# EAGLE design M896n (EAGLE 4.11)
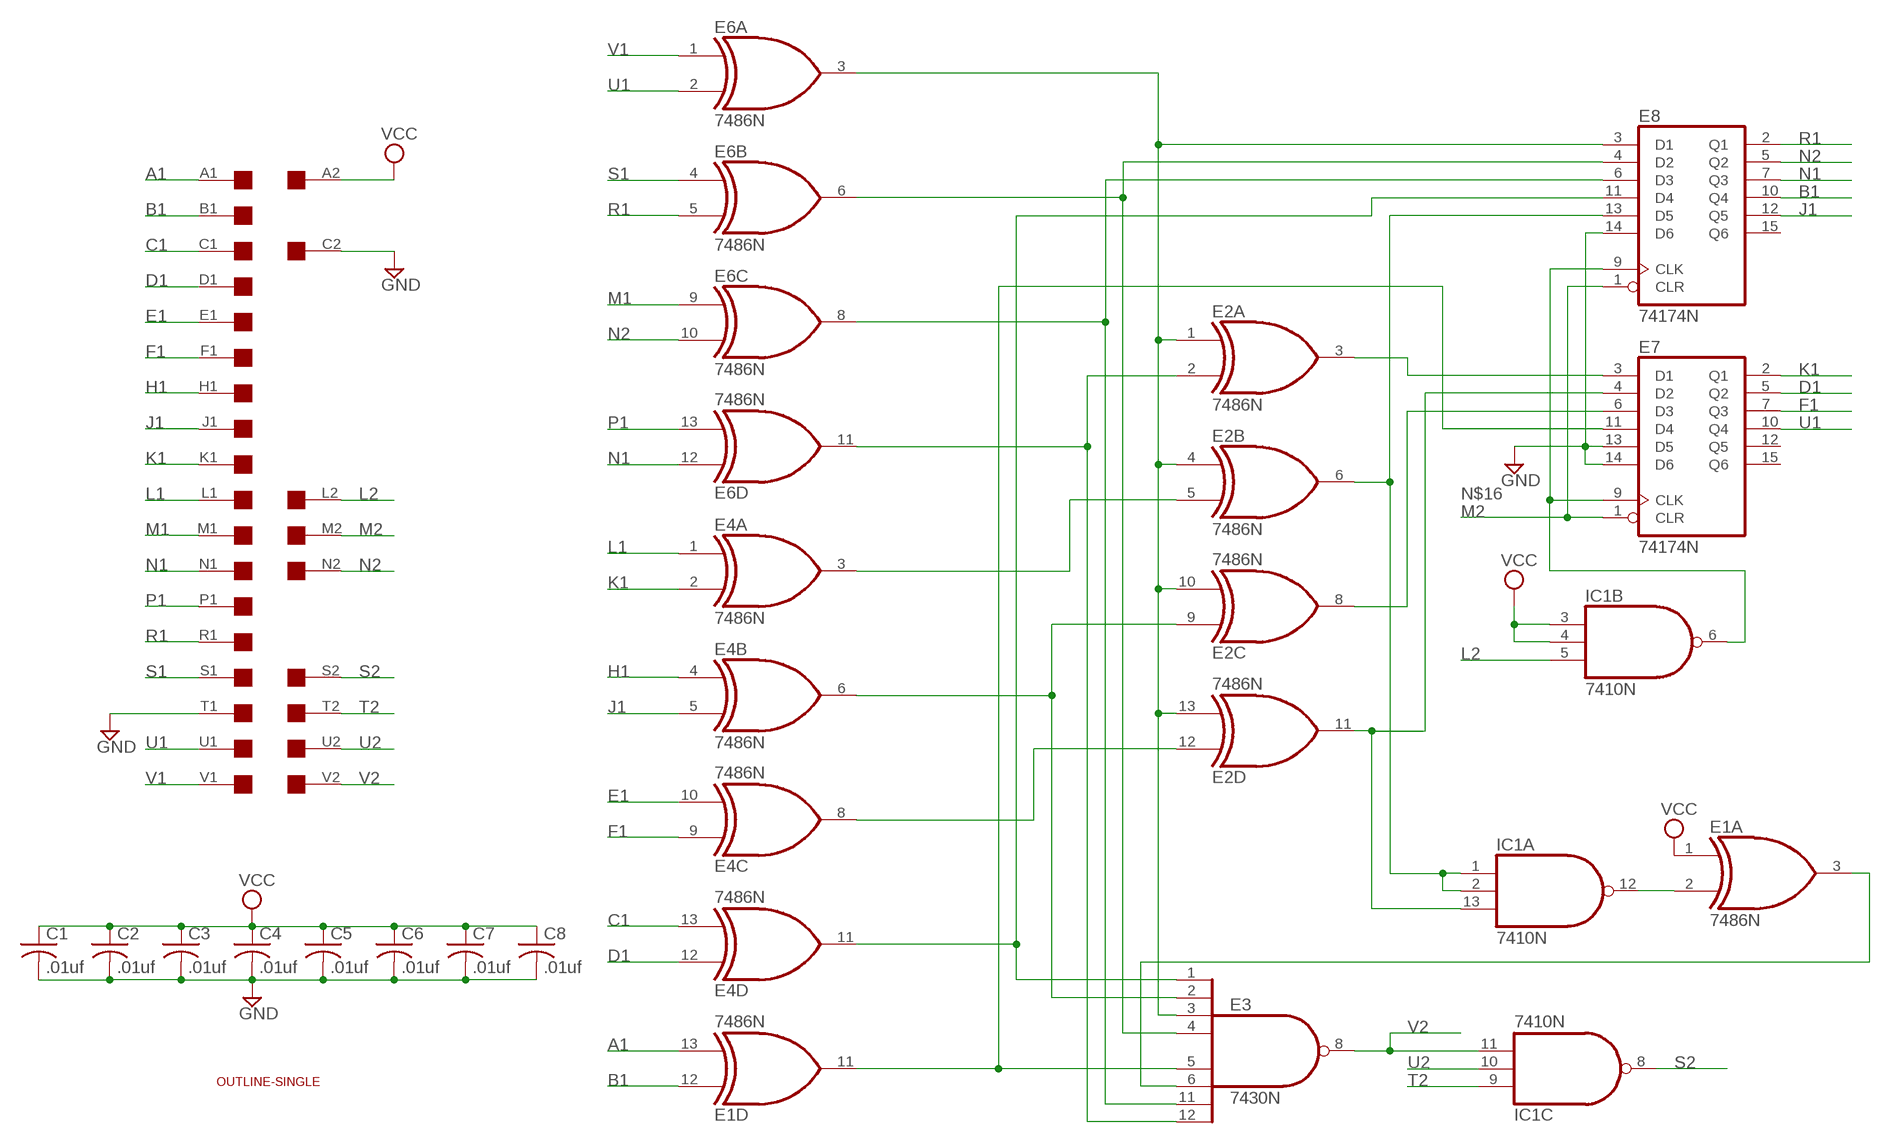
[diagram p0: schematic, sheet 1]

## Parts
C1  .01uf  C-US050-025X075  [C050-025X075]
C2  .01uf  C-US050-025X075  [C050-025X075]
C3  .01uf  C-US050-025X075  [C050-025X075]
C4  .01uf  C-US050-025X075  [C050-025X075]
C5  .01uf  C-US050-025X075  [C050-025X075]
C6  .01uf  C-US050-025X075  [C050-025X075]
C7  .01uf  C-US050-025X075  [C050-025X075]
C8  .01uf  C-US050-025X075  [C050-025X075]
E1  7486N  [DIL14]
E2  7486N  [DIL14]
E3  7430N  [DIL14]
E4  7486N  [DIL14]
E6  7486N  [DIL14]
E7  74174N  [DIL16]
E8  74174N  [DIL16]
IC1  7410N  [DIL14]
U$1  EDGE-2CONNECTOR  [EDGE-CON2]
U$4  OUTLINE-SINGLE  [SINGLE]

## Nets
A1: E1.13(D:I1) U$1.A1
B1: E1.12(D:I0) E8.10(Q4) U$1.B1
C1: E4.13(D:I1) U$1.C1
D1: E4.12(D:I0) E7.5(Q2) U$1.D1
E1: E4.10(C:I1) U$1.E1
F1: E4.9(C:I0) E7.7(Q3) U$1.F1
GND [power]: C1.2 C2.2 C3.2 C4.2 C5.2 C6.2 C7.2 C8.2 E7.13(D5) E7.14(D6) E8.14(D6) U$1.C2 U$1.T1
H1: E4.4(B:I0) U$1.H1
J1: E4.5(B:I1) E8.12(Q5) U$1.J1
K1: E4.2(A:I1) E7.2(Q1) U$1.K1
L1: E4.1(A:I0) U$1.L1
L2: IC1.5(B:I2) U$1.L2
M1: E6.9(C:I0) U$1.M1
M2: E7.1(CLR) E8.1(CLR) U$1.M2
N1: E6.12(D:I0) E8.7(Q3) U$1.N1
N2: E6.10(C:I1) E8.5(Q2) U$1.N2
N$1: E2.1(A:I0) E2.4(B:I0) E2.10(C:I1) E2.13(D:I1) E3.3(I2) E6.3(A:O) E8.3(D1)
N$2: E2.2(A:I1) E3.12(I7) E6.11(D:O)
N$3: E2.5(B:I1) E4.3(A:O)
N$4: E2.9(C:I0) E3.2(I1) E4.6(B:O)
N$5: E2.12(D:I0) E4.8(C:O)
N$6: E1.11(D:O) E3.5(I4) E7.11(D4)
N$7: E3.1(I0) E4.11(D:O) E8.11(D4)
N$8: E1.2(A:I1) IC1.12(A:O)
N$9: E3.11(I6) E6.8(C:O) E8.6(D3)
N$10: E3.4(I3) E6.6(B:O) E8.4(D2)
N$11: E1.3(A:O) E3.6(I5)
N$12: E2.6(B:O) E8.13(D5) IC1.1(A:I0) IC1.2(A:I1)
N$13: E2.11(D:O) E7.4(D2) IC1.13(A:I2)
N$14: E2.3(A:O) E7.3(D1)
N$15: E2.8(C:O) E7.6(D3)
N$16: E7.9(CLK) E8.9(CLK) IC1.6(B:O)
P1: E6.13(D:I1) U$1.P1
R1: E6.5(B:I1) E8.2(Q1) U$1.R1
S1: E6.4(B:I0) U$1.S1
S2: IC1.8(C:O) U$1.S2
T2: IC1.9(C:I0) U$1.T2
U1: E6.2(A:I1) E7.10(Q4) U$1.U1
U2: IC1.10(C:I1) U$1.U2
V1: E6.1(A:I0) U$1.V1
V2: E3.8(O) IC1.11(C:I2) U$1.V2
VCC [power]: C1.1 C2.1 C3.1 C4.1 C5.1 C6.1 C7.1 C8.1 E1.1(A:I0) IC1.3(B:I0) IC1.4(B:I1) U$1.A2
Unconnected: E1.4(B:I0) E1.5(B:I1) E1.6(B:O) E1.8(C:O) E1.9(C:I0) E1.10(C:I1) E7.12(Q5) E7.15(Q6) E8.15(Q6) U$1.B2 U$1.D2 U$1.E2 U$1.F2 U$1.H2 U$1.J2 U$1.K2 U$1.P2 U$1.R2

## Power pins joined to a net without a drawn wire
GND: E1.7(P:GND) E2.7(P:GND) E3.7(GND) E4.7(P:GND) E6.7(P:GND) E7.8(GND) E8.8(GND) IC1.7(P:GND)
VCC: E1.14(P:VCC) E2.14(P:VCC) E3.14(VCC) E4.14(P:VCC) E6.14(P:VCC) E7.16(VCC) E8.16(VCC) IC1.14(P:VCC)

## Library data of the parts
C1-C8 = rcl:C-US: CAPACITOR, American symbol
E1 E2 E4 E6 = 74xx-jameco:74*86: Quad 2-input EXCLUSIV-OR (XOR) gate
E3 = 74xx-jameco:74*30: 8-input NAND gate
E7 E8 = 74xx-jameco:74*174: Hex D type FLIP FLOP, clear
IC1 = 74xx-jameco:74*10: Triple 3-input NAND gate
U$1 = dec-con:EDGE-2: Double-Sided DEC edge connector.
U$4 = dec-con:OUTLINE-*: Board outlines for DEC boards.

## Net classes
1 power: width 0.508 mm

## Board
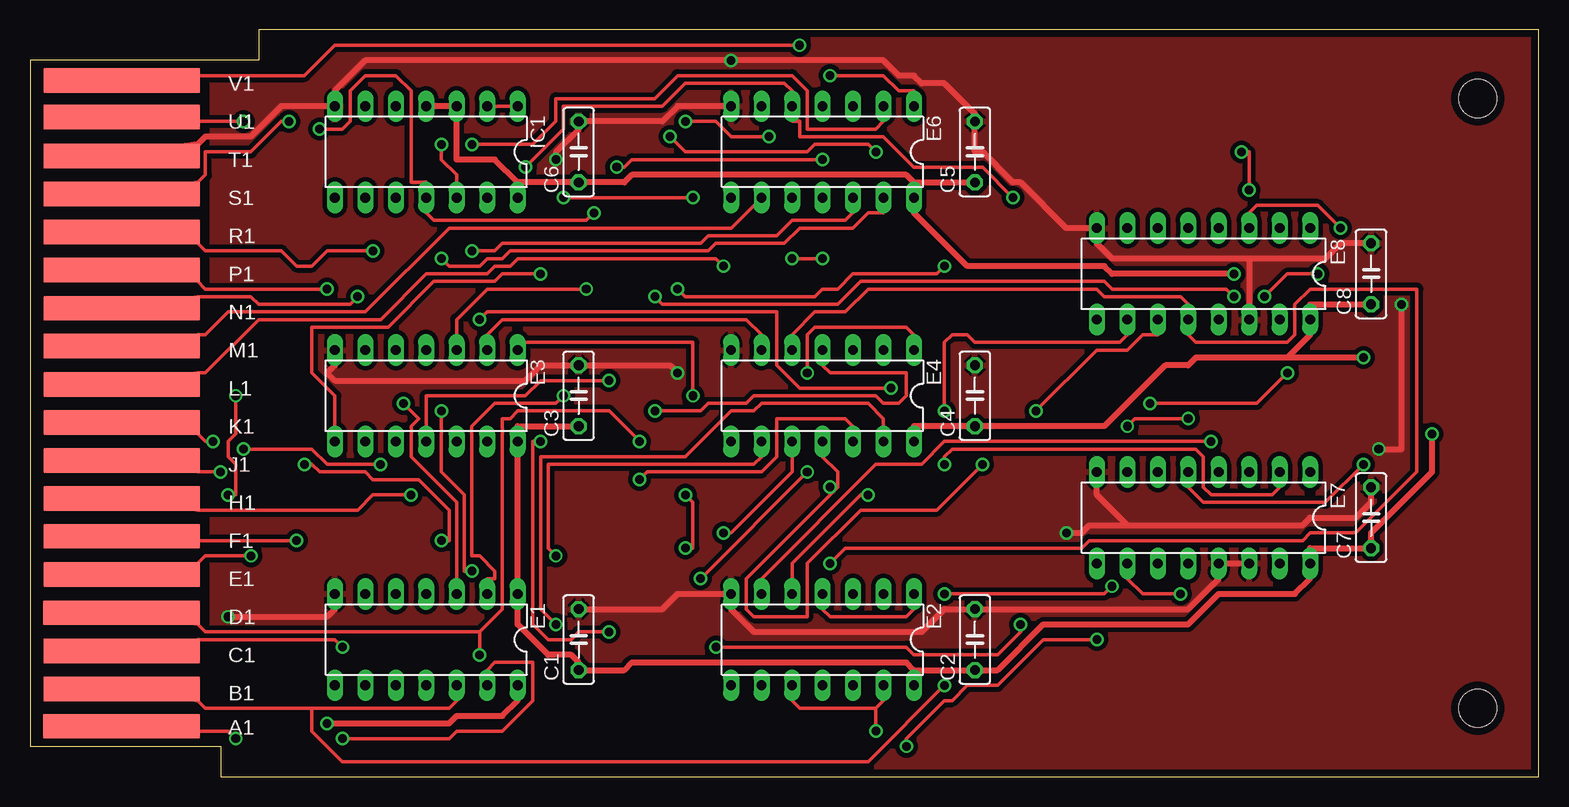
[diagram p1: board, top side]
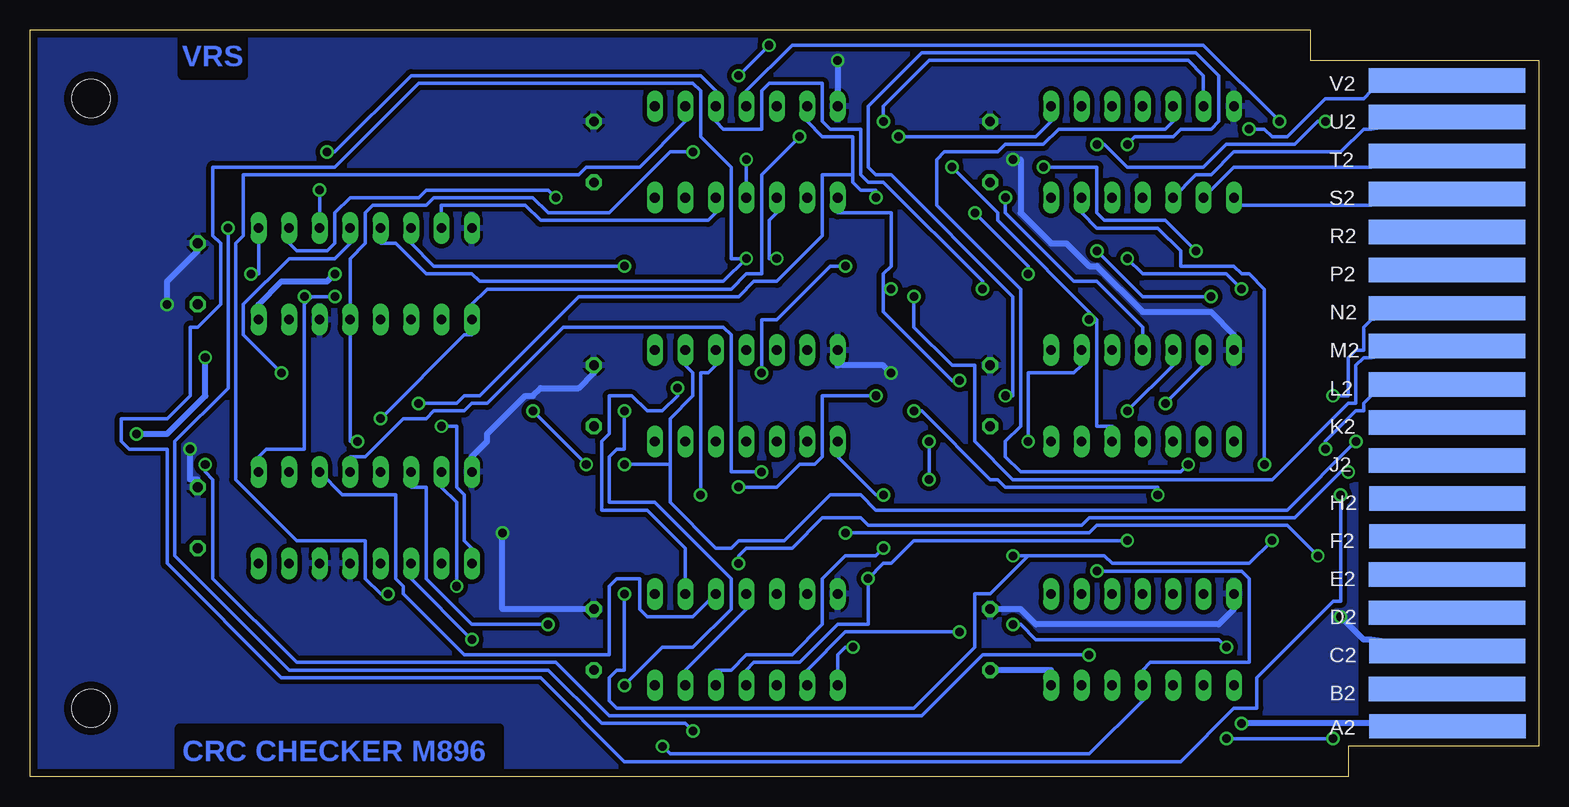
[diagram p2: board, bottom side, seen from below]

Size 125.73 x 62.23 mm. Coordinates in mm from the lower left corner, seen from the top.
Copper layers (1*16): Top 0.035mm / dielectric 1.5mm / Bottom 0.035mm
Design rules "10mils": minimum track width 12mil, minimum drill 28mil, track to track 10mil, track to pad 10mil, pad to pad 10mil, via to via 10mil, smd to smd 10mil, copper to edge 25mil, drill to drill 10mil, minimum pad ring 10mil, minimum via ring 8mil, stop-mask expansion 0mil, vias tented up to drill 0mil, thermal gap 10mil
bRestrict: area 108,58.4 to 113,62.2; area 86.6,0.3 to 113.3,4.1

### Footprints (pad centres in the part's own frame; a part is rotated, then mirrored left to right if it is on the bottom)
C050-025X075 = drill 0.813 octagon: 1 -2.54,0; 2 2.54,0
DIL14 = drill 0.813 long: 1 -7.62,-3.81; 2 -5.08,-3.81; 3 -2.54,-3.81; 4 0,-3.81; 5 2.54,-3.81; 6 5.08,-3.81; 7 7.62,-3.81; 8 7.62,3.81; 9 5.08,3.81; 10 2.54,3.81; 11 0,3.81; 12 -2.54,3.81; 13 -5.08,3.81; 14 -7.62,3.81
DIL16 = drill 0.813 long: 1 -8.89,-3.81; 2 -6.35,-3.81; 3 -3.81,-3.81; 4 -1.27,-3.81; 5 1.27,-3.81; 6 3.81,-3.81; 7 6.35,-3.81; 8 8.89,-3.81; 9 8.89,3.81; 10 6.35,3.81; 11 3.81,3.81; 12 1.27,3.81; 13 -1.27,3.81; 14 -3.81,3.81; 15 -6.35,3.81; 16 -8.89,3.81
EDGE-CON2 = smd 13.017 x 2.032: A1 7.633,4.207; B1 7.639,7.327; C1 7.636,10.489; D1 7.633,13.665; E1 7.642,16.84; F1 7.642,20.041; H1 7.642,23.19; J1 7.642,26.34; K1 7.642,29.515; L1 7.642,32.69; M1 7.642,35.89; N1 7.642,39.04; P1 7.642,42.24; R1 7.642,45.39; S1 7.642,48.565; T1 7.642,51.74; U1 7.642,54.966; V1 7.642,58.026 | smd 13.017 x 2.032 bottom: A2 7.614,4.207; B2 7.642,7.328; C2 7.617,10.49; D2 7.642,13.665; E2 7.642,16.84; F2 7.617,20.041; H2 7.617,23.19; J2 7.642,26.34; K2 7.642,29.515; L2 7.642,32.69; M2 7.642,35.89; N2 7.642,39.04; P2 7.642,42.24; R2 7.642,45.39; S2 7.642,48.565; T2 7.642,51.74; U2 7.642,54.966; V2 7.642,58.026
SINGLE = hole 3.175: 120.65,56.515; 120.65,5.715

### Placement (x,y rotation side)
C1  45.72,11.43 90 top
C2  78.74,11.43 90 top
C3  45.72,31.75 90 top
C4  78.74,31.75 90 top
C5  78.74,52.07 90 top
C6  45.72,52.07 90 top
C7  111.76,21.59 90 top
C8  111.76,41.91 90 top
E1  33.02,11.43 180 top
E2  66.04,11.43 180 top
E3  33.02,31.75 180 top
E4  66.04,31.75 180 top
E6  66.04,52.07 180 top
E7  97.79,21.59 180 top
E8  97.79,41.91 180 top
IC1  33.02,52.07 180 top
U$1  0,0 0 top
U$4  0,0 0 top

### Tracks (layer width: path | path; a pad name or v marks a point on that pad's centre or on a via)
A1  (via drill 0.71)
  Top 0.305: v17.15,3.17 16.51,3.81 13.97,3.81 U$1.A1 | v26.04,3.17 34.93,3.17 35.56,3.81 39.37,3.81 41.91,6.35 41.91,9.53 38.74,9.53 38.1,8.89 E1.13
  Bottom 0.305: v17.15,3.17 v26.04,3.17
B1  (via drill 0.71)
  Top 0.305: 23.5,5.71 34.93,5.71 35.56,6.35 E1.12 | 23.5,5.71 14.61,5.71 13.97,6.35 U$1.B1 | v76.2,30.48 76.2,36.2 76.84,36.83 78.11,36.83 78.74,36.2 90.81,36.2 91.44,36.83 E8.10 | v76.2,7.62 69.85,1.27 26.04,1.27 23.5,3.81 23.5,5.71
  Bottom 0.305: v76.2,30.48 76.2,27.3 76.84,27.3 77.47,26.67 77.47,22.86 73.66,22.86 67.31,16.51 67.31,13.97 70.49,10.79 73.03,10.79 v76.2,7.62
C1  (via drill 0.71)
  Top 0.305: v26.04,10.79 25.4,11.43 13.97,11.43 U$1.C1 | v43.82,12.7 42.55,13.97 42.55,26.67 54.61,26.67 58.42,30.48 60.33,30.48 60.96,31.11 69.85,31.11 71.12,29.84 E4.13
  Bottom 0.305: v26.04,10.79 26.67,11.43 41.91,11.43 43.18,12.7 v43.82,12.7
D1  (via drill 0.71)
  Top 0.305: 37.47,12.06 14.61,12.06 13.97,12.7 U$1.D1 | 37.47,12.06 39.37,13.97 39.37,29.84 40.01,29.84 40.64,30.48 48.26,30.48 v50.8,27.94 | v50.8,24.77 51.44,25.4 60.96,25.4 62.23,26.67 62.23,29.84 67.95,29.84 68.58,29.21 E4.12 | v111.13,26.04 107.95,22.86 97.79,22.86 96.52,24.13 E7.5 | 37.47,12.06 v37.47,10.16
  Bottom 0.305: v50.8,27.94 v50.8,24.77 | v111.13,26.04 111.13,25.4 110.49,24.77 110.49,16.51 103.51,9.53 81.92,9.53 77.47,5.08 51.44,5.08 46.36,10.16 v37.47,10.16
E1  (via drill 0.71)
  Top 0.305: v18.42,18.41 14.61,18.41 13.97,17.78 U$1.E1 | v57.79,20.32 58.42,20.32 63.5,25.4 E4.10
  Bottom 0.305: v18.42,18.41 20.96,20.95 36.83,20.95 37.47,20.32 v57.79,20.32
F1  (via drill 0.71)
  Top 0.305: v22.23,19.68 13.97,19.68 U$1.F1 | v43.82,18.41 43.18,19.05 43.18,26.04 60.33,26.04 60.96,26.67 E4.9 | v90.17,15.88 89.54,15.24 v76.2,15.24
  Bottom 0.305: v22.23,19.68 24.13,17.78 35.56,17.78 36.2,18.41 42.55,18.41 | 42.55,18.41 v43.82,18.41 | v90.17,15.88 90.17,22.86 91.44,24.13 E7.7 | v76.2,15.24 76.2,8.89 76.84,8.89 77.47,8.26 77.47,6.35 76.84,5.71 52.07,5.71 46.99,10.79 46.99,15.24 45.72,15.24 42.55,18.41
GND  (via drill 0.71)
  Top 0.508: 101.6,43.18 107.95,43.18 109.22,44.45 C8.2 | 101.6,43.18 90.17,43.18 88.9,44.45 E8.8 86.36,45.72 82.55,49.53 81.92,49.53 79.38,52.07 78.74,52.07 C5.2 78.74,55.24 76.2,57.78 74.3,57.78 73.66,58.42 72.39,58.42 71.12,59.69 v58.42,59.69 27.94,59.69 25.4,57.15 IC1.7 20.96,55.88 18.42,53.34 14.61,53.34 13.97,52.7 U$1.T1 | 101.6,43.18 E8.14 | E3.7 25.4,34.29 24.77,33.66 25.4,33.02 41.28,33.02 42.55,34.29 C3.2 53.34,34.29 v53.98,33.66 | E6.7 53.98,55.88 52.71,54.61 C6.2 45.72,53.98 43.82,52.07 v43.82,51.44 | 91.44,20.95 106.05,20.95 106.68,21.59 110.49,21.59 111.76,22.86 C7.2 | 91.44,20.95 88.9,23.5 E7.8 | v16.51,13.34 24.77,13.34 25.4,13.97 E1.7 | C1.2 52.71,13.97 53.98,15.24 E2.7 58.42,13.97 60.33,12.06 74.3,12.06 76.2,13.97 C2.2 96.52,13.97 99.06,16.51 E7.13 E7.14 | 91.44,20.95 88.27,20.95 87.63,20.32 v86.36,20.32 | v114.3,39.37 114.3,27.3 v112.4,27.3
  Bottom 0.508: v53.98,33.66 54.61,34.29 58.42,34.29 E4.7 | v58.42,59.69 E6.7 | v43.82,51.44 43.18,51.44 43.18,46.99 40.64,44.45 39.37,44.45 37.47,42.55 36.83,42.55 33.02,38.73 27.31,38.73 25.4,36.83 E3.7 | C4.2 78.74,33.66 80.01,32.38 83.19,32.38 83.82,31.75 84.46,31.75 87.63,28.57 87.63,27.94 88.9,26.67 E7.8 | v16.51,13.34 14.61,11.43 13.97,11.43 U$1.C2 | E1.7 25.4,13.97 26.67,12.7 41.91,12.7 43.18,13.97 C1.2 | v86.36,20.32 86.36,13.97 C2.2 | v114.3,39.37 114.3,41.27 111.76,43.81 C8.2 | v112.4,27.3 112.4,24.77 111.76,24.77 C7.2
  pour Top (isolate 0.381): 15.24,62.23 125.73,62.23 125.73,0 15.24,0
  pour Bottom (isolate 0.381): 15.24,62.23 125.73,62.23 125.73,0 15.24,0
H1  (via drill 0.71)
  Top 0.305: v31.75,23.5 28.58,23.5 27.31,22.23 13.97,22.23 U$1.H1 | v52.07,30.48 55.88,30.48 56.52,31.11 59.69,31.11 60.33,31.75 70.49,31.75 71.12,31.11 72.39,31.11 73.03,31.75 73.03,33.66 66.68,33.66 66.04,34.29 E4.4
  Bottom 0.305: v31.75,23.5 31.75,24.13 44.45,24.13 45.09,24.77 45.72,24.77 51.44,30.48 v52.07,30.48
J1  (via drill 0.71)
  Top 0.305: v15.88,25.4 13.97,25.4 U$1.J1 | v66.68,17.78 67.95,19.05 87.63,19.05 88.27,19.68 106.05,19.68 106.68,20.32 110.49,20.32 115.57,25.4 115.57,40.64 106.68,40.64 105.41,39.37 105.41,36.83 104.78,36.2 97.16,36.2 96.52,36.83 E8.12 96.52,39.37 95.89,40.01 89.54,40.01 88.9,40.64 69.85,40.64 67.95,38.73 65.41,38.73 63.5,36.83 E4.5
  Bottom 0.305: v15.88,25.4 16.51,25.4 20.32,21.59 37.47,21.59 38.1,20.95 55.88,20.95 56.52,21.59 59.69,21.59 62.23,19.05 66.04,19.05 66.68,18.41 v66.68,17.78
K1  (via drill 0.71)
  Top 0.305: v15.24,27.94 14.61,27.94 13.97,28.57 U$1.K1 | v76.2,26.04 76.2,26.67 76.84,27.3 97.16,27.3 97.79,26.67 97.79,24.13 98.43,23.5 103.51,23.5 104.14,24.13 E7.2
  Bottom 0.305: v15.24,27.94 20.96,22.23 55.25,22.23 56.52,23.5 59.06,23.5 62.87,19.68 66.68,19.68 67.31,19.05 68.58,19.05 72.39,22.86 72.39,26.04 | 72.39,26.04 72.39,29.84 70.49,31.75 70.49,33.66 71.12,34.29 E4.2 | 72.39,26.04 v76.2,26.04
L1  (via drill 0.71)
  Top 0.305: v64.77,33.66 64.77,36.83 65.41,37.47 73.03,37.47 73.66,36.83 E4.1 | v57.79,42.55 57.15,43.18 40.64,43.18 40.01,42.55 38.74,42.55 38.1,41.91 33.02,41.91 29.21,38.1 19.05,38.1 14.61,33.66 13.97,33.66 U$1.L1
  Bottom 0.305: v64.77,33.66 64.77,38.1 63.5,38.1 59.06,42.55 v57.79,42.55
L2  (via drill 0.71)
  Top 0.305: v17.78,27.3 23.5,27.3 24.77,26.04 v29.21,26.04
  Bottom 0.305: v17.78,27.3 17.78,27.94 15.24,30.48 14.61,30.48 14.61,31.11 13.97,31.75 U$1.L2 | v29.21,26.04 29.85,25.4 43.18,25.4 44.45,26.67 44.45,27.94 43.18,29.21 43.18,40.64 50.17,47.62 50.17,51.44 49.53,52.07 45.09,52.07 44.45,52.7 41.28,52.7 40.01,53.98 31.12,53.98 30.48,54.61 IC1.5
M1
  Top 0.305: E6.9 58.42,45.72 34.93,45.72 27.94,38.73 16.51,38.73 14.61,36.83 13.97,36.83 U$1.M1
M2  (via drill 0.71)
  Top 0.305: v52.07,40.01 52.71,39.37 67.31,39.37 69.22,41.27 89.54,41.27 90.17,40.64 99.7,40.64 v100.33,40.01 | v107.32,41.91 104.78,41.91 v102.87,40.01
  Bottom 0.305: v52.07,40.01 52.07,37.47 48.9,34.29 46.99,34.29 46.99,27.94 43.82,24.77 22.23,24.77 15.88,31.11 15.24,31.11 15.24,34.29 14.61,34.92 13.97,34.92 U$1.M2 | v100.33,40.01 102.24,40.01 | 102.24,40.01 102.87,39.37 102.87,27.3 106.05,27.3 106.68,26.67 E7.1 | v107.32,41.91 106.68,41.91 E8.1 | 102.24,40.01 v102.87,40.01
N1  (via drill 0.71)
  Top 0.305: v27.31,40.01 26.67,39.37 19.05,39.37 18.42,40.01 13.97,40.01 U$1.N1 | v36.83,43.81 38.74,43.81 39.37,44.45 55.88,44.45 56.52,45.09 62.23,45.09 63.5,46.35 67.95,46.35 68.58,46.99 E6.12
  Bottom 0.305: v27.31,40.01 33.02,40.01 v36.83,43.81 | E8.7 91.44,47.62 84.46,47.62 83.19,46.35 69.22,46.35 68.58,46.99 E6.12
N2  (via drill 0.71)
  Top 0.305: v66.04,43.18 v63.5,43.18 | v17.15,31.75 17.15,28.57 16.51,27.94 16.51,26.67 17.15,26.04 17.15,23.5 v16.51,23.5
  Bottom 0.305: v63.5,43.18 64.14,43.18 64.14,46.35 63.5,46.99 E6.10 | E8.5 96.52,44.45 95.25,44.45 92.71,41.91 88.9,41.91 88.27,41.27 67.95,41.27 v66.04,43.18 67.31,43.18 67.31,50.8 69.85,53.34 69.85,57.15 70.49,57.78 93.35,57.78 100.33,50.8 110.49,50.8 110.49,45.09 109.86,44.45 109.86,39.37 111.76,37.47 112.4,37.47 112.4,31.75 114.3,29.84 118.11,29.84 118.11,27.94 117.48,27.3 114.3,27.3 114.3,17.78 104.78,8.26 83.19,8.26 76.2,1.27 29.85,1.27 25.4,5.71 23.5,5.71 23.5,8.26 17.15,14.61 16.51,14.61 v16.51,23.5 | v17.15,31.75 15.88,31.75 15.88,34.92 15.24,35.56 14.61,35.56 14.61,37.47 13.97,38.1 U$1.N2
N$1  (via drill 0.71)
  Top 0.305: 70.49,5.71 64.14,5.71 63.5,6.35 E2.10 | 70.49,5.71 71.12,6.35 E2.13 | E2.4 66.04,13.97 66.68,13.34 73.03,13.34 73.66,13.97 E2.1 | v101.6,48.9 101.6,52.07 v100.97,52.07 | v46.36,40.64 38.1,40.64 35.56,38.1 E3.3 | 70.49,5.71 v70.49,3.81 | v109.22,45.72 107.32,47.62 102.24,47.62 101.6,46.99 E8.3
  Bottom 0.305: E2.13 71.12,8.89 66.04,13.97 E2.4 | v100.97,52.07 100.33,52.07 93.98,58.42 69.85,58.42 68.58,57.15 E6.3 68.58,54.61 67.95,53.98 64.77,53.98 64.77,57.15 64.14,57.78 59.69,57.78 59.69,54.61 59.06,53.98 56.52,53.98 56.52,50.16 55.88,49.53 54.61,49.53 46.36,41.27 v46.36,40.64 | E8.3 v101.6,48.9 | v70.49,3.81 71.12,4.45 78.11,4.45 82.55,8.89 104.14,8.89 113.67,18.41 113.67,27.94 109.22,32.38 v109.22,45.72
N$2  (via drill 0.71)
  Top 0.305: v66.04,51.44 50.17,51.44 49.53,50.8 v48.9,50.8 | v71.76,32.38 64.14,32.38 62.23,34.29 62.23,38.73 38.1,38.73 v37.47,38.1
  Bottom 0.305: v48.9,50.8 45.09,46.99 45.09,46.35 36.83,38.1 | 36.83,38.1 36.83,29.21 35.56,29.21 E3.12 | v66.04,51.44 E6.11 | v71.76,32.38 71.76,31.75 73.03,30.48 74.3,30.48 75.57,31.75 77.47,31.75 77.47,28.57 78.11,27.94 78.11,22.23 74.3,22.23 71.12,19.05 E2.2 | 36.83,38.1 v37.47,38.1
N$3  (via drill 0.71)
  Top 0.305: v69.85,23.5 69.22,23.5 63.5,17.78 E2.5
  Bottom 0.305: v69.85,23.5 69.85,33.66 69.22,33.66 68.58,34.29 E4.3
N$4  (via drill 0.71)
  Top 0.305: E4.6 60.96,36.83 59.69,38.1 39.37,38.1 38.1,36.83 E3.2 | v48.26,12.06 45.72,12.06 45.09,11.43 43.18,11.43 41.91,12.7 41.91,27.94 v42.55,27.94
  Bottom 0.305: v48.26,12.06 57.79,12.06 60.96,8.89 E2.9 | v42.55,27.94 42.55,33.66 38.74,33.66 38.1,34.29 E3.2
N$5  (via drill 0.71)
  Top 0.305: v54.61,23.5 55.25,22.86 55.25,19.05 v54.61,19.05
  Bottom 0.305: v54.61,23.5 55.25,23.5 58.42,26.67 E4.8 | v54.61,19.05 55.25,18.41 57.79,18.41 59.69,16.51 59.69,12.7 62.23,10.16 66.04,10.16 67.31,8.89 68.58,8.89 E2.12
N$6  (via drill 0.71)
  Top 0.305: v73.03,2.54 73.03,3.17 76.2,6.35 76.84,6.35 78.11,7.62 80.65,7.62 84.46,11.43 v88.9,11.43 | v34.29,30.48 34.29,25.4 36.2,23.5 36.2,17.14 v36.83,17.14
  Bottom 0.305: v73.03,2.54 72.39,1.91 37.47,1.91 33.02,6.35 E1.11 33.02,8.89 32.39,9.53 24.13,9.53 24.13,16.51 24.77,17.14 v36.83,17.14 | v88.9,11.43 93.98,16.51 E7.11 | v34.29,30.48 30.48,34.29 E3.5
N$7  (via drill 0.71)
  Top 0.305: 67.31,24.13 67.31,25.4 66.04,26.67 E4.11 | 67.31,24.13 v66.68,24.13 | v55.25,31.75 55.25,36.2 41.28,36.2 E3.1 | v83.82,30.48 88.9,35.56 91.44,35.56 92.71,36.83 93.98,36.83 E8.11 | v79.38,26.04 75.57,22.23 69.22,22.23 64.77,17.78 64.77,13.34 60.33,13.34 59.69,13.97 59.69,16.51 67.31,24.13
  Bottom 0.305: v66.68,24.13 63.5,24.13 61.6,26.04 60.33,26.04 59.69,26.67 59.69,31.75 v55.25,31.75 | v79.38,26.04 v83.82,30.48
N$8  (via drill 0.71)
  Top 0.305: v34.29,52.7 34.29,51.44 35.56,50.16 IC1.12 | v44.45,31.75 43.82,31.11 38.74,31.11 36.83,29.21 36.83,18.41 37.47,18.41 38.74,17.14 38.74,16.51 38.1,16.51 E1.2
  Bottom 0.305: v34.29,52.7 33.66,53.34 30.48,53.34 29.85,53.98 27.31,53.98 26.67,54.61 26.67,58.42 28.58,60.33 51.44,60.33 55.88,55.88 55.88,50.8 55.25,50.16 53.98,50.16 43.82,40.01 43.82,31.75 v44.45,31.75
N$9  (via drill 0.71)
  Top 0.305: v48.26,33.02 42.55,33.02 41.28,31.75 33.02,31.75 E3.11 | v76.2,42.55 75.57,41.91 68.58,41.91 67.31,40.64 66.04,40.64 65.41,40.01 54.61,40.01 v53.98,40.64
  Bottom 0.305: v48.26,33.02 48.9,33.02 54.61,38.73 54.61,40.64 | 54.61,40.64 54.61,41.91 53.98,42.55 53.98,46.99 58.42,46.99 E6.8 | v76.2,42.55 92.08,42.55 93.98,44.45 E8.6 | 54.61,40.64 v53.98,40.64
N$10  (via drill 0.71)
  Top 0.305: v44.45,48.26 v55.25,48.26 | v104.78,33.66 102.24,31.11 v93.35,31.11
  Bottom 0.305: v44.45,48.26 44.45,46.99 38.74,41.27 36.83,41.27 33.02,37.47 E3.4 | v55.25,48.26 55.25,48.9 56.52,48.9 57.15,49.53 57.15,50.16 | 57.15,50.16 57.15,53.34 59.69,53.34 60.96,54.61 E6.6 | v104.78,33.66 107.95,36.83 107.95,39.37 104.14,43.18 100.33,43.18 99.06,44.45 E8.4 | v93.35,31.11 90.17,31.11 89.54,31.75 88.27,31.75 80.01,40.01 66.68,40.01 65.41,41.27 63.5,41.27 59.69,45.09 59.69,50.16 57.15,50.16
N$11  (via drill 0.71)
  Top 0.305: v31.12,31.11 32.39,29.84 31.75,29.21 31.75,26.67 35.56,22.86 E1.3
  Bottom 0.305: v31.12,31.11 27.94,34.29 E3.6
N$12  (via drill 0.71)
  Top 0.305: IC1.1 IC1.2 | v98.43,27.94 76.2,27.94 74.3,26.04 70.49,26.04 60.96,16.51 E2.6 | v53.34,53.34 54.61,52.07 64.77,52.07 65.41,52.7 69.85,52.7 v70.49,52.07
  Bottom 0.305: v98.43,27.94 99.06,27.94 E8.13 99.06,43.18 97.79,44.45 97.79,46.99 97.16,47.62 92.71,47.62 92.08,48.26 83.82,48.26 82.55,46.99 77.47,46.99 72.39,52.07 v70.49,52.07 | v53.34,53.34 41.91,53.34 40.64,54.61 IC1.1
N$13  (via drill 0.71)
  Top 0.305: v55.88,16.51 v64.77,25.4 | v22.86,26.04 23.5,26.04 24.13,25.4 27.94,25.4 28.58,24.77 32.39,24.77 34.93,22.23 34.93,19.68 v34.29,19.68
  Bottom 0.305: v64.77,25.4 67.31,25.4 67.31,36.83 67.95,37.47 81.28,37.47 87.63,31.11 88.9,31.11 89.54,30.48 92.08,30.48 92.71,29.84 94.62,29.84 97.79,26.67 99.06,26.67 E7.4 | E2.11 66.04,8.89 65.41,9.53 61.6,9.53 58.42,12.7 55.88,12.7 v55.88,16.51 54.61,17.78 53.98,17.78 52.07,19.68 v34.29,19.68 | v22.86,26.04 22.86,40.64 24.13,41.91 24.77,41.91 25.4,42.55 29.85,42.55 29.85,43.81 31.75,45.72 36.83,45.72 38.1,46.99 IC1.13
N$14
  Bottom 0.305: E2.3 70.49,13.34 74.3,13.34 74.93,13.97 74.93,16.51 76.84,16.51 77.47,15.88 77.47,10.16 89.54,10.16 94.62,15.24 94.62,15.88 95.25,16.51 95.25,23.5 99.7,23.5 E7.3
N$15  (via drill 0.71)
  Top 0.305: v57.15,10.79 73.03,10.79 73.66,10.16 80.65,10.16 82.55,12.06 v82.55,12.7
  Bottom 0.305: v57.15,10.79 57.79,10.79 58.42,10.16 E2.8 | v82.55,12.7 88.9,12.7 92.71,16.51 92.71,24.13 93.98,24.13 E7.6
N$16  (via drill 0.71)
  Top 0.305: v91.44,29.21 92.08,29.84 v96.52,29.84 | v54.61,54.61 57.15,54.61 58.42,53.34 v61.6,53.34
  Bottom 0.305: v91.44,29.21 90.17,29.21 90.17,24.13 89.54,23.5 89.54,19.68 88.9,19.05 E7.9 | v96.52,29.84 89.54,36.83 88.9,36.83 E8.9 88.9,39.37 87.63,40.64 67.31,40.64 66.04,41.91 64.77,41.91 64.77,50.16 v61.6,53.34 | v54.61,54.61 54.61,55.88 50.8,59.69 29.21,59.69 27.94,58.42 IC1.6
P1  (via drill 0.71)
  Top 0.305: v24.77,40.64 14.61,40.64 13.97,41.27 U$1.P1 | v34.29,43.18 34.93,42.55 37.47,42.55 38.1,43.18 39.37,43.18 40.01,43.81 56.52,43.81 57.15,44.45 62.87,44.45 64.14,45.72 68.58,45.72 69.85,46.99 71.12,46.99 E6.13
  Bottom 0.305: v24.77,40.64 26.04,41.91 33.02,41.91 v34.29,43.18
R1  (via drill 0.71)
  Top 0.305: v28.58,43.81 24.77,43.81 23.5,42.55 22.23,42.55 20.96,43.81 14.61,43.81 13.97,44.45 U$1.R1 | v41.28,50.8 44.45,53.98 44.45,55.88 52.71,55.88 54.61,57.78 62.87,57.78 63.5,57.15 E6.5 63.5,54.61 64.14,54.61 64.14,53.34 71.12,53.34 73.66,50.8 79.38,50.8 v81.92,48.26
  Bottom 0.305: v28.58,43.81 31.12,46.35 36.2,46.35 36.83,46.99 36.83,50.8 v41.28,50.8 | v81.92,48.26 82.55,48.9 92.71,48.9 93.35,48.26 99.06,48.26 100.33,46.99 100.33,44.45 100.97,43.81 103.51,43.81 104.14,44.45 E8.2
S1  (via drill 0.71)
  Top 0.305: v21.59,54.61 20.96,54.61 18.42,52.07 14.61,52.07 14.61,50.16 13.97,49.53 U$1.S1
  Bottom 0.305: v21.59,54.61 27.94,60.96 62.23,60.96 66.04,57.15 E6.4
S2
  Bottom 0.305: IC1.8 24.77,47.62 13.97,47.62 U$1.S2
T2
  Bottom 0.305: IC1.9 25.4,50.8 13.97,50.8 U$1.T2
U1  (via drill 0.71)
  Top 0.305: v17.78,54.61 13.97,54.61 U$1.U1 | v36.83,52.7 41.91,52.7 43.82,54.61 43.82,56.52 52.07,56.52 53.98,58.42 63.5,58.42 64.77,57.15 64.77,53.98 70.49,53.98 71.12,54.61 E6.2 | v95.89,15.24 92.71,15.24 91.44,16.51 E7.10
  Bottom 0.305: v17.78,54.61 18.42,54.61 20.32,52.7 26.04,52.7 27.94,50.8 34.29,50.8 36.2,52.7 v36.83,52.7 | v95.89,15.24 96.52,15.24 97.79,16.51 97.79,19.68 103.51,19.68 108.59,24.77 108.59,44.45 107.95,45.09 107.95,50.16 80.01,50.16 79.38,50.8 74.93,50.8 71.12,54.61 E6.2
U2
  Bottom 0.305: IC1.10 28.58,50.16 27.31,50.16 25.4,52.07 16.51,52.07 14.61,53.98 13.97,53.98 U$1.U2
V1  (via drill 0.71)
  Top 0.305: v66.68,58.42 71.12,58.42 72.39,57.15 73.66,57.15 E6.1 | v64.14,60.96 25.4,60.96 22.86,58.42 13.97,58.42 U$1.V1
  Bottom 0.305: v64.14,60.96 v66.68,58.42
V2  (via drill 0.71)
  Top 0.305: v24.13,53.98 26.04,53.98 26.67,54.61 26.67,57.15 27.94,58.42 30.48,58.42 31.75,57.15 31.75,49.53 33.02,49.53 IC1.11 33.02,46.99 33.66,46.35 46.36,46.35 v46.99,46.99 | v42.55,41.91 39.37,41.91 38.74,41.27 33.66,41.27 29.85,37.47 23.5,37.47 23.5,33.66 25.4,31.75 E3.8
  Bottom 0.305: v24.13,53.98 22.86,53.98 22.23,53.34 20.96,53.34 17.78,56.52 14.61,56.52 13.97,57.15 U$1.V2 | v42.55,41.91 42.55,42.55 v46.99,46.99
VCC  (via drill 0.71)
  Top 0.508: E4.14 73.66,29.21 C4.1 89.54,29.21 94.62,34.29 96.52,34.29 97.16,34.92 104.78,34.92 | C8.1 106.68,39.37 E8.16 106.68,36.83 104.78,34.92 | 73.66,49.53 C5.1 | IC1.4 IC1.3 35.56,51.44 38.74,51.44 40.64,49.53 | 40.64,49.53 C6.1 49.53,49.53 50.17,50.16 73.03,50.16 73.66,49.53 | 40.64,49.53 IC1.14 | 73.66,49.53 E6.14 73.66,46.99 78.11,42.55 89.54,42.55 90.17,41.91 v100.33,41.91 | C3.1 40.64,29.21 E3.14 E1.1 40.64,12.7 43.18,10.16 45.09,10.16 45.72,9.53 C1.1 49.53,8.89 50.17,9.53 73.03,9.53 73.66,8.89 | 73.66,8.89 C2.1 80.65,8.89 84.46,12.7 96.52,12.7 99.06,15.24 105.41,15.24 106.68,16.51 E7.16 106.68,19.05 C7.1 111.76,20.32 116.84,25.4 v116.84,28.57 | v24.77,4.45 34.93,4.45 35.56,5.08 39.37,5.08 40.64,6.35 E1.14 | 73.66,8.89 E2.14 | v111.13,34.92 104.78,34.92
  Bottom 0.508: v100.33,41.91 100.97,41.27 104.78,41.27 106.68,39.37 E8.16 | v24.77,4.45 13.97,4.45 U$1.A2 | C1.1 40.64,8.89 E1.14 | v111.13,34.92 111.13,31.75 114.3,28.57 v116.84,28.57

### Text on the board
Bottom: VRS | CRC CHECKER M896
